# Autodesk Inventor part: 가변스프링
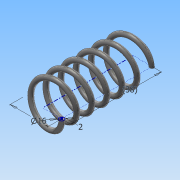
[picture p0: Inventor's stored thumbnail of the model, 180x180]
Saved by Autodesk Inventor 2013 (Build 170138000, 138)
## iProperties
Created: 2017-06
Part Number: 가변스프링
Material: 강철, 탄소
Document SubType Name: Modeling
Designer: Administrator
Density: 7.87 g/cm^3
Mass: 7.34047 g
Surface Area: 18.9697 cm^2
Volume: 0.932715 cm^3
Author: Administrator
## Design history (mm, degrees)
sketch "스케치1"
  geometry: L1 (0, 0)-(8, 0); L2 (8, 0)-(8, 38); L3 (8, 38)-(0, 38); L4 (0, 38)-(0, 0); C1 r 1 at (8, 0)
  constraints: 8 end point, 2 parallel, 1 centre point, 1 coincident, 1 horizontal, 1 perpendicular
  dimensions: "d0" = 16 diameter of L2 L4; "d2" = 38 distance of L1.end L2.end (derived); "d3" = 2 diameter of C1
feature "코일1" sketch "스케치1" pitch "d4" = 10; turns "d6" = 6; dims "d5" = 38 (= d2), "d7" = 0, angle "d8" = 90 deg, angle "d9" = 90 deg, "d10" = 0, "d11" = 0
sketch "스케치2"
  geometry: L1 (39, 0)-(37, 0) reference; L2 (-1, 0)-(1, 0) reference; L3 (38, 24.641)-(0, 24.641); L4 (0, 24.641)-(0, -24.641); L5 (0, -24.641)-(38, -24.641); L6 (38, -24.641)-(38, 24.641); 5 further points
  constraints: 8 end point, 4 midpoint, 2 parallel, 1 horizontal, 1 horizontal alignment, 1 perpendicular
extrude "돌출1" sketch "스케치2" stored distance "d12" = 50; taper "d13" = 0 deg
node "솔리드1"
node "투영된 루프1"
